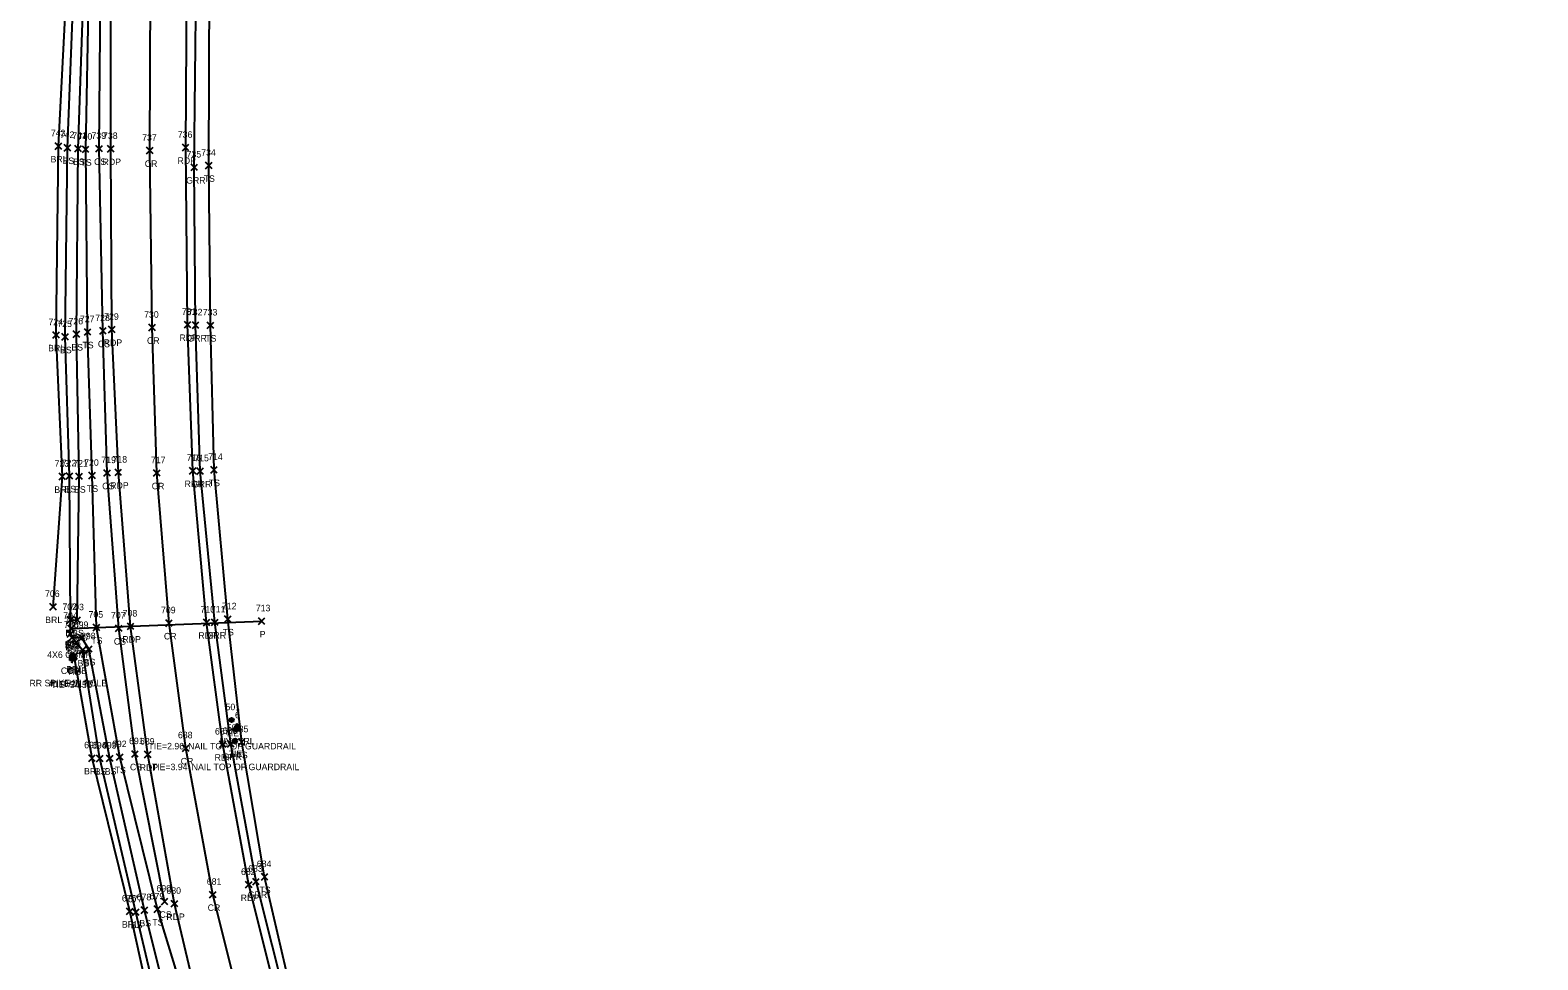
# Model space of a CAD drawing. Extents: x 1879695 to 1880991, y 836466 to 845172.
# Drawn here: x 1879776.2 to 1880237.6, y 844585 to 844869.6 of the extents above; entities that cross this region are included whole.
import ezdxf

# ---------------------------------------------------------------- set-up
doc = ezdxf.new("R2010")
doc.units = 0
for name, color, linetype in [('C_A', 7, 'Continuous'), ('C_C', 7, 'Continuous'), ('C_I', 7, 'Continuous'), ('CBP', 7, 'Continuous'), ('CPBM', 7, 'Continuous'), ('CPSM', 7, 'Continuous'), ('D_A', 7, 'Continuous'), ('D_C', 7, 'Continuous'), ('D_I', 7, 'Continuous'), ('D_TIC', 7, 'Continuous'), ('DCP', 7, 'Continuous'), ('L_A', 7, 'Continuous'), ('L_I', 7, 'Continuous'), ('L_TIC', 7, 'Continuous'), ('LABL', 7, 'Continuous'), ('LELB', 7, 'Continuous'), ('P_A', 7, 'Continuous'), ('P_I', 7, 'Continuous'), ('P_TIC', 7, 'Continuous'), ('PET', 7, 'Continuous'), ('PRC', 7, 'Continuous'), ('R_A', 7, 'Continuous'), ('R_I', 7, 'Continuous'), ('R_TIC', 7, 'Continuous'), ('RGR', 7, 'Continuous'), ('U_A', 7, 'Continuous'), ('U_C', 7, 'Continuous'), ('U_I', 7, 'Continuous'), ('UP', 7, 'Continuous')]:
    doc.layers.add(name, color=color, linetype=linetype)

msp = doc.modelspace()

# ---------------------------------------------------------------- linework, layer by layer
at = {"layer": 'CBP'}
for centre, radius in [((1879789.35, 844677.24), 0.625), ((1879789.35, 844677.24), 0.0833), ((1879837.9, 844658.44), 0.625), ((1879837.9, 844658.44), 0.0833), ((1879838.92, 844652.09), 0.625), ((1879838.92, 844652.09), 0.0833)]:
    msp.add_circle(centre, radius, dxfattribs=at)
at = {"layer": 'CPBM'}
for p, q in [((1879788.92, 844677.25), (1879788.92, 844678.25)), ((1879788.92, 844678.25), (1879789.92, 844678.25)), ((1879789.92, 844677.25), (1879788.92, 844677.25)), ((1879789.42, 844677.75), (1879789.42, 844677.75)), ((1879789.42, 844677.75), (1879789.42, 844677.75)), ((1879789.92, 844678.25), (1879789.92, 844677.25))]:
    msp.add_line(p, q, dxfattribs=at)
at = {"layer": 'CPSM'}
for p, q in [((1879838.29, 844655.25), (1879839.54, 844657.42)), ((1879840.79, 844655.25), (1879839.54, 844657.42)), ((1879839.54, 844655.97), (1879839.54, 844657.42)), ((1879838.29, 844655.25), (1879839.54, 844655.97)), ((1879838.29, 844655.25), (1879840.79, 844655.25)), ((1879839.54, 844655.97), (1879839.54, 844655.97)), ((1879839.54, 844655.97), (1879840.79, 844655.25))]:
    msp.add_line(p, q, dxfattribs=at)
at = {"layer": 'D_TIC'}
for points in [[(1879846.09, 844687.71), (1879848.09, 844689.71)], [(1879848.09, 844687.71), (1879846.09, 844689.71)], [(1879787.78, 844685.43), (1879789.78, 844687.43)], [(1879789.78, 844685.43), (1879787.78, 844687.43)]]:
    msp.add_lwpolyline(points, dxfattribs=at)
at = {"layer": 'DCP'}
msp.add_lwpolyline([(1879788.78, 844686.43), (1879847.09, 844688.71)], dxfattribs=at)
at = {"layer": 'L_TIC'}
for points in [[(1879783.93, 844833.09), (1879785.93, 844835.09)], [(1879785.93, 844833.09), (1879783.93, 844835.09)], [(1879786.69, 844832.58), (1879788.69, 844834.58)], [(1879788.69, 844832.58), (1879786.69, 844834.58)], [(1879789.9, 844832.29), (1879791.9, 844834.29)], [(1879791.9, 844832.29), (1879789.9, 844834.29)], [(1879792.24, 844832.08), (1879794.24, 844834.08)], [(1879794.24, 844832.08), (1879792.24, 844834.08)], [(1879796.37, 844832.31), (1879798.37, 844834.31)], [(1879798.37, 844832.31), (1879796.37, 844834.31)], [(1879829.94, 844827.14), (1879831.94, 844829.14)], [(1879831.94, 844827.14), (1879829.94, 844829.14)], [(1879783.2, 844775.27), (1879785.2, 844777.27)], [(1879785.2, 844775.27), (1879783.2, 844777.27)], [(1879785.93, 844774.7), (1879787.93, 844776.7)], [(1879787.93, 844774.7), (1879785.93, 844776.7)], [(1879789.4, 844775.52), (1879791.4, 844777.52)], [(1879791.4, 844775.52), (1879789.4, 844777.52)], [(1879792.83, 844776.19), (1879794.83, 844778.19)], [(1879794.83, 844776.19), (1879792.83, 844778.19)], [(1879797.52, 844776.54), (1879799.52, 844778.54)], [(1879799.52, 844776.54), (1879797.52, 844778.54)], [(1879830.42, 844778.25), (1879832.42, 844780.25)], [(1879832.42, 844778.25), (1879830.42, 844780.25)], [(1879798.83, 844733.05), (1879800.83, 844735.05)], [(1879800.83, 844733.05), (1879798.83, 844735.05)], [(1879831.5, 844734.02), (1879833.5, 844736.02)], [(1879833.5, 844734.02), (1879831.5, 844736.02)], [(1879785.09, 844731.95), (1879787.09, 844733.95)], [(1879787.09, 844731.95), (1879785.09, 844733.95)], [(1879787.25, 844732.11), (1879789.25, 844734.11)], [(1879789.25, 844732.11), (1879787.25, 844734.11)], [(1879790.23, 844732), (1879792.23, 844734)], [(1879792.23, 844732), (1879790.23, 844734)], [(1879794.21, 844732.25), (1879796.21, 844734.25)], [(1879796.21, 844732.25), (1879794.21, 844734.25)], [(1879782.28, 844692.1), (1879784.28, 844694.1)], [(1879784.28, 844692.1), (1879782.28, 844694.1)], [(1879787.56, 844688.11), (1879789.56, 844690.11)], [(1879789.56, 844688.11), (1879787.56, 844690.11)], [(1879787.56, 844688.11), (1879789.56, 844690.11)], [(1879789.56, 844688.11), (1879787.56, 844690.11)], [(1879789.67, 844688.03), (1879791.67, 844690.03)], [(1879791.67, 844688.03), (1879789.67, 844690.03)], [(1879835.74, 844688.33), (1879837.74, 844690.33)], [(1879837.74, 844688.33), (1879835.74, 844690.33)], [(1879787.58, 844683.77), (1879789.58, 844685.77)], [(1879789.58, 844683.77), (1879787.58, 844685.77)], [(1879788.08, 844682.63), (1879790.08, 844684.63)], [(1879790.08, 844682.63), (1879788.08, 844684.63)], [(1879788.08, 844682.63), (1879790.08, 844684.63)], [(1879790.08, 844682.63), (1879788.08, 844684.63)], [(1879791.03, 844682.6), (1879793.03, 844684.6)], [(1879793.03, 844682.6), (1879791.03, 844684.6)], [(1879795.55, 844685.76), (1879797.55, 844687.76)], [(1879797.55, 844685.76), (1879795.55, 844687.76)], [(1879802.4, 844685.5), (1879804.4, 844687.5)], [(1879804.4, 844685.5), (1879802.4, 844687.5)], [(1879791.29, 844678.84), (1879793.29, 844680.84)], [(1879793.29, 844678.84), (1879791.29, 844680.84)], [(1879793.2, 844679.16), (1879795.2, 844681.16)], [(1879795.2, 844679.16), (1879793.2, 844681.16)], [(1879788.74, 844676.99), (1879790.74, 844678.99)], [(1879790.74, 844676.99), (1879788.74, 844678.99)], [(1879839.98, 844650.69), (1879841.98, 844652.69)], [(1879841.98, 844650.69), (1879839.98, 844652.69)], [(1879794.18, 844645.79), (1879796.18, 844647.79)], [(1879796.18, 844645.79), (1879794.18, 844647.79)], [(1879796.58, 844645.67), (1879798.58, 844647.67)], [(1879798.58, 844645.67), (1879796.58, 844647.67)], [(1879799.64, 844645.71), (1879801.64, 844647.71)], [(1879801.64, 844645.71), (1879799.64, 844647.71)], [(1879802.7, 844646.13), (1879804.7, 844648.13)], [(1879804.7, 844646.13), (1879802.7, 844648.13)], [(1879807.34, 844647.05), (1879809.34, 844649.05)], [(1879809.34, 844647.05), (1879807.34, 844649.05)], [(1879847, 844609.42), (1879849, 844611.42)], [(1879849, 844609.42), (1879847, 844611.42)], [(1879810.24, 844599.26), (1879812.24, 844601.26)], [(1879812.24, 844599.26), (1879810.24, 844601.26)], [(1879814.22, 844599.52), (1879816.22, 844601.52)], [(1879816.22, 844599.52), (1879814.22, 844601.52)], [(1879816.39, 844601.91), (1879818.39, 844603.91)], [(1879818.39, 844601.91), (1879816.39, 844603.91)], [(1879805.77, 844598.89), (1879807.77, 844600.89)], [(1879807.77, 844598.89), (1879805.77, 844600.89)], [(1879807.57, 844598.66), (1879809.57, 844600.66)], [(1879809.57, 844598.66), (1879807.57, 844600.66)]]:
    msp.add_lwpolyline(points, dxfattribs=at)
at = {"layer": 'LABL'}
for points in [[(1879783.28, 844693.1), (1879786.09, 844732.95), (1879784.2, 844776.27), (1879784.93, 844834.09), (1879787.31, 844881.75), (1879789.94, 844927.36), (1879791.41, 844971.14), (1879790.38, 845013.26), (1879792.98, 845052.42), (1879793.87, 845087.6), (1879791.51, 845127.71), (1879794.05, 845166.9)], [(1879838.84, 844478.29), (1879827.4, 844514.75), (1879815.43, 844560.66), (1879806.77, 844599.89), (1879795.18, 844646.79), (1879789.74, 844677.99)]]:
    msp.add_lwpolyline(points, dxfattribs=at)
at = {"layer": 'LELB'}
for points in [[(1879788.56, 844689.11), (1879788.25, 844733.11), (1879786.93, 844775.7), (1879787.69, 844833.58), (1879789.53, 844880.94), (1879792.57, 844929), (1879794.18, 844969.53), (1879792.62, 845014.23), (1879795.86, 845051.75), (1879795.49, 845087.45), (1879795.44, 845126.23), (1879796.98, 845166.46)], [(1879840.74, 844478.66), (1879829.75, 844515.78), (1879817.77, 844560.78), (1879808.57, 844599.66), (1879797.58, 844646.67), (1879792.29, 844679.84), (1879789.08, 844683.63), (1879788.58, 844684.77), (1879788.56, 844689.11), (1879790.67, 844689.03), (1879791.23, 844733), (1879790.4, 844776.52), (1879790.9, 844833.29), (1879792.57, 844880.83), (1879794.66, 844928.51), (1879796.6, 844970.46), (1879795.45, 845013.86), (1879797.69, 845051.68), (1879797.82, 845087.62), (1879798.32, 845126.29), (1879799.71, 845166.01)], [(1879826.86, 844562.48), (1879815.22, 844600.52), (1879803.7, 844647.13), (1879796.55, 844686.76), (1879795.21, 844733.25), (1879793.83, 844777.19), (1879793.24, 844833.08), (1879794.22, 844881.27), (1879796.97, 844928.77), (1879797.73, 844970.48), (1879796.62, 845014.48), (1879799.04, 845050.66), (1879799.3, 845087.57), (1879800.29, 845126.59), (1879801.38, 845165.98)], [(1879892.86, 844475.33), (1879883.81, 844493.88), (1879869.59, 844531.53), (1879857.27, 844570.41), (1879848, 844610.42), (1879840.98, 844651.69), (1879836.74, 844689.33), (1879832.5, 844735.02), (1879831.42, 844779.25), (1879830.94, 844828.14), (1879831.12, 844883.89), (1879831.78, 844926.93), (1879832.17, 844972.31), (1879832.24, 845014.04), (1879832.59, 845051.89), (1879833.37, 845086.82), (1879834.06, 845125.48), (1879835.58, 845163.13)], [(1879817.39, 844602.91), (1879808.34, 844648.05), (1879803.4, 844686.5), (1879799.83, 844734.05), (1879798.52, 844777.54), (1879797.37, 844833.31), (1879797.81, 844880.47), (1879798.76, 844929.8), (1879800.12, 844970.52), (1879800.28, 845015.67), (1879801.11, 845051.3), (1879801.14, 845087.72), (1879800.29, 845126.59)], [(1880237.65, 844030.17), (1880225.55, 844045.25), (1880203.19, 844067.94), (1880175.04, 844095.38), (1880141.55, 844124.24), (1880111.59, 844152.12), (1880079.67, 844179.09), (1880044.89, 844208.16), (1880013.5, 844237.54), (1880003.34, 844247.82), (1879979.16, 844270.62), (1879948.51, 844300.87), (1879928.97, 844335.67), (1879901.59, 844373.87), (1879881.39, 844405.75), (1879863.37, 844445.07), (1879846.41, 844479.41), (1879833.35, 844517.23), (1879821, 844560.9), (1879811.24, 844600.26), (1879800.64, 844646.71), (1879794.2, 844680.16), (1879792.03, 844683.6), (1879789.08, 844683.63)]]:
    msp.add_lwpolyline(points, dxfattribs=at)
at = {"layer": 'P_TIC'}
for points in [[(1879799.91, 844832.26), (1879801.91, 844834.26)], [(1879801.91, 844832.26), (1879799.91, 844834.26)], [(1879811.88, 844831.71), (1879813.88, 844833.71)], [(1879813.88, 844831.71), (1879811.88, 844833.71)], [(1879822.84, 844832.63), (1879824.84, 844834.63)], [(1879824.84, 844832.63), (1879822.84, 844834.63)], [(1879800.26, 844776.93), (1879802.26, 844778.93)], [(1879802.26, 844776.93), (1879800.26, 844778.93)], [(1879812.56, 844777.55), (1879814.56, 844779.55)], [(1879814.56, 844777.55), (1879812.56, 844779.55)], [(1879823.44, 844778.44), (1879825.44, 844780.44)], [(1879825.44, 844778.44), (1879823.44, 844780.44)], [(1879802.24, 844733.23), (1879804.24, 844735.23)], [(1879804.24, 844733.23), (1879802.24, 844735.23)], [(1879814.01, 844733.04), (1879816.01, 844735.04)], [(1879816.01, 844733.04), (1879814.01, 844735.04)], [(1879825.01, 844733.72), (1879827.01, 844735.72)], [(1879827.01, 844733.72), (1879825.01, 844735.72)], [(1879817.74, 844687.1), (1879819.74, 844689.1)], [(1879819.74, 844687.1), (1879817.74, 844689.1)], [(1879829.24, 844687.3), (1879831.24, 844689.3)], [(1879831.24, 844687.3), (1879829.24, 844689.3)], [(1879805.99, 844686.11), (1879807.99, 844688.11)], [(1879807.99, 844686.11), (1879805.99, 844688.11)], [(1879834.2, 844649.98), (1879836.2, 844651.98)], [(1879836.2, 844649.98), (1879834.2, 844651.98)], [(1879811.27, 844646.91), (1879813.27, 844648.91)], [(1879813.27, 844646.91), (1879811.27, 844648.91)], [(1879822.88, 844648.84), (1879824.88, 844650.84)], [(1879824.88, 844648.84), (1879822.88, 844650.84)], [(1879831.13, 844604), (1879833.13, 844606)], [(1879833.13, 844604), (1879831.13, 844606)], [(1879842.17, 844607.03), (1879844.17, 844609.03)], [(1879844.17, 844607.03), (1879842.17, 844609.03)], [(1879819.43, 844601.23), (1879821.43, 844603.23)], [(1879821.43, 844601.23), (1879819.43, 844603.23)]]:
    msp.add_lwpolyline(points, dxfattribs=at)
at = {"layer": 'PET'}
for points in [[(1879829.6, 844563.28), (1879820.43, 844602.23), (1879812.27, 844647.91), (1879806.99, 844687.11), (1879803.24, 844734.23), (1879801.26, 844777.93), (1879800.91, 844833.26), (1879800.95, 844881.46), (1879801.81, 844930.36), (1879801.95, 844971.12), (1879802.52, 845016.02), (1879802.87, 845051.39), (1879803.55, 845087.63), (1879804.52, 845126.21), (1879806.13, 845165.3)], [(1879852.88, 844569.32), (1879843.17, 844608.03), (1879835.2, 844650.98), (1879830.24, 844688.3), (1879826.01, 844734.72), (1879824.44, 844779.44), (1879823.84, 844833.63), (1879824.22, 844883.19), (1879824.83, 844927), (1879825.18, 844971.93), (1879825.59, 845014.41), (1879826.07, 845051.35), (1879826.48, 845086.56), (1879827.38, 845125.9), (1879829.31, 845162.92)]]:
    msp.add_lwpolyline(points, dxfattribs=at)
at = {"layer": 'PRC'}
msp.add_lwpolyline([(1879841.81, 844566.38), (1879832.13, 844605), (1879823.88, 844649.84), (1879818.74, 844688.1), (1879815.01, 844734.04), (1879813.56, 844778.55), (1879812.88, 844832.71), (1879813.07, 844881.95), (1879813.15, 844927.66), (1879813.64, 844971.27), (1879814, 845015.87), (1879814.47, 845051.81), (1879815.09, 845086.96), (1879816.12, 845125.8), (1879818.34, 845164.04)], dxfattribs=at)
at = {"layer": 'R_TIC'}
for points in [[(1879825.48, 844826.6), (1879827.48, 844828.6)], [(1879827.48, 844826.6), (1879825.48, 844828.6)], [(1879825.87, 844778.28), (1879827.87, 844780.28)], [(1879827.87, 844778.28), (1879825.87, 844780.28)], [(1879827.26, 844733.62), (1879829.26, 844735.62)], [(1879829.26, 844733.62), (1879827.26, 844735.62)], [(1879831.76, 844687.35), (1879833.76, 844689.35)], [(1879833.76, 844687.35), (1879831.76, 844689.35)], [(1879836.63, 844650.18), (1879838.63, 844652.18)], [(1879838.63, 844650.18), (1879836.63, 844652.18)], [(1879844.36, 844607.98), (1879846.36, 844609.98)], [(1879846.36, 844607.98), (1879844.36, 844609.98)]]:
    msp.add_lwpolyline(points, dxfattribs=at)
at = {"layer": 'RGR'}
msp.add_lwpolyline([(1879855.21, 844570.01), (1879845.36, 844608.98), (1879837.63, 844651.18), (1879832.76, 844688.35), (1879828.26, 844734.62), (1879826.87, 844779.28), (1879826.48, 844827.6), (1879827.03, 844883.27), (1879827.42, 844927.16), (1879828.14, 844972.18), (1879828.58, 845014.65), (1879828.78, 845051.84), (1879829.43, 845086.81), (1879829.88, 845125.96), (1879831.63, 845162.98)], dxfattribs=at)
at = {"layer": 'UP'}
for p, q in [((1879788.41, 844676.69), (1879788.41, 844678.36)), ((1879788.41, 844678.36), (1879790.08, 844678.36)), ((1879790.08, 844676.69), (1879788.41, 844676.69)), ((1879789, 844675.86), (1879789.25, 844676.69)), ((1879789.5, 844679.19), (1879789.25, 844678.36)), ((1879789.25, 844677.52), (1879789.25, 844677.52)), ((1879790.08, 844678.36), (1879790.08, 844676.69))]:
    msp.add_line(p, q, dxfattribs=at)
msp.add_circle((1879789.25, 844677.52), 0.833, dxfattribs=at)

# ---------------------------------------------------------------- texts
at = {"layer": 'C_A'}
for s, p in [('TIE', (1879787.42, 844672.24)), ('BM', (1879787.73, 844672.75)), ('HVCTRL', (1879834.23, 844650.97)), ('TIE', (1879835.98, 844653.44)), ('TIE', (1879836.99, 844647.09))]:
    msp.add_text(s, height=2, dxfattribs=at).set_placement(p)
at = {"layer": 'C_C'}
for s, p in [('RR SPIKE IN POLE', (1879776.02, 844668.75)), ("TIE=54.51'", (1879782.65, 844668.24)), ("TIE=2.96' NAIL TOP OF GUARDRAIL", (1879812.42, 844649.44)), ("TIE=3.94' NAIL TOP OF GUARDRAIL", (1879813.48, 844643.09))]:
    msp.add_text(s, height=2, dxfattribs=at).set_placement(p)
at = {"layer": 'C_I'}
for s, p in [('502', (1879786.9, 844680.24)), ('826', (1879787, 844680.75)), ('501', (1879836.03, 844661.44)), ('500', (1879836.39, 844655.09)), ('6', (1879838.92, 844658.97))]:
    msp.add_text(s, height=2, dxfattribs=at).set_placement(p)
at = {"layer": 'D_A'}
for p in [(1879846.47, 844683.71), (1879788.16, 844681.43)]:
    msp.add_text('P', height=2, dxfattribs=at).set_placement(p)
at = {"layer": 'D_C'}
msp.add_text('4X6 CGMP', height=2, dxfattribs=at).set_placement((1879781.45, 844677.43))
at = {"layer": 'D_I'}
for s, p in [('713', (1879845.29, 844691.71)), ('704', (1879786.34, 844689.43))]:
    msp.add_text(s, height=2, dxfattribs=at).set_placement(p)
at = {"layer": 'L_A'}
for s, p in [('BRL', (1879782.48, 844829.09)), ('BS', (1879786.13, 844828.58)), ('BS', (1879789.34, 844828.29)), ('TS', (1879791.65, 844828.08)), ('CS', (1879795.81, 844828.31)), ('TS', (1879829.35, 844823.14)), ('BRL', (1879781.74, 844771.27)), ('BS', (1879785.37, 844770.7)), ('BS', (1879788.84, 844771.52)), ('TS', (1879792.24, 844772.19)), ('CS', (1879796.96, 844772.54)), ('TS', (1879829.83, 844774.25)), ('CS', (1879798.27, 844729.05)), ('TS', (1879830.91, 844730.02)), ('BRL', (1879783.63, 844727.95)), ('BS', (1879786.7, 844728.11)), ('BS', (1879789.67, 844728)), ('TS', (1879793.62, 844728.25)), ('BRL', (1879780.83, 844688.1)), ('BS', (1879787, 844684.11)), ('BS', (1879787, 844684.11)), ('BS', (1879789.11, 844684.03)), ('TS', (1879835.15, 844684.33)), ('BS', (1879787.02, 844679.77)), ('BS', (1879787.52, 844678.63)), ('BS', (1879787.52, 844678.63)), ('BS', (1879790.47, 844678.6)), ('TS', (1879794.96, 844681.76)), ('CS', (1879801.84, 844681.5)), ('BS', (1879790.74, 844674.84)), ('BS', (1879792.64, 844675.16)), ('BRL', (1879787.29, 844672.99)), ('TS', (1879839.39, 844646.69)), ('BRL', (1879792.72, 844641.79)), ('BS', (1879796.02, 844641.67)), ('BS', (1879799.08, 844641.71)), ('TS', (1879802.11, 844642.13)), ('CS', (1879806.78, 844643.05)), ('TS', (1879846.41, 844605.42)), ('BRL', (1879804.31, 844594.89)), ('BS', (1879807.01, 844594.66)), ('BS', (1879809.68, 844595.26)), ('TS', (1879813.63, 844595.52)), ('CS', (1879815.83, 844597.91))]:
    msp.add_text(s, height=2, dxfattribs=at).set_placement(p)
at = {"layer": 'L_I'}
for s, p in [('743', (1879782.57, 844837.09)), ('742', (1879785.33, 844836.58)), ('741', (1879789.11, 844836.29)), ('740', (1879790.79, 844836.08)), ('739', (1879795, 844836.31)), ('734', (1879828.58, 844831.14)), ('724', (1879781.84, 844779.27)), ('726', (1879787.98, 844779.52)), ('727', (1879791.47, 844780.19)), ('728', (1879796.15, 844780.54)), ('733', (1879829.06, 844782.25)), ('725', (1879784.56, 844778.7)), ('714', (1879830.7, 844738.02)), ('723', (1879783.73, 844735.95)), ('722', (1879785.89, 844736.11)), ('721', (1879789.43, 844736)), ('720', (1879792.76, 844736.25)), ('719', (1879798.03, 844737.05)), ('706', (1879780.79, 844696.1)), ('702', (1879786.12, 844692.11)), ('702', (1879786.12, 844692.11)), ('703', (1879788.22, 844692.03)), ('712', (1879834.94, 844692.33)), ('701', (1879786.71, 844687.77)), ('705', (1879794.11, 844689.76)), ('707', (1879800.96, 844689.5)), ('700', (1879786.55, 844686.63)), ('700', (1879786.55, 844686.63)), ('699', (1879789.61, 844686.6)), ('697', (1879789.89, 844682.84)), ('698', (1879791.79, 844683.16)), ('696', (1879787.28, 844680.99)), ('685', (1879838.57, 844654.69)), ('692', (1879801.29, 844650.13)), ('691', (1879806.5, 844651.05)), ('695', (1879792.77, 844649.79)), ('694', (1879795.17, 844649.67)), ('693', (1879798.23, 844649.71)), ('684', (1879845.59, 844613.42)), ('690', (1879814.89, 844605.91)), ('676', (1879804.3, 844602.89)), ('677', (1879806.16, 844602.66)), ('678', (1879808.83, 844603.26)), ('679', (1879812.8, 844603.52))]:
    msp.add_text(s, height=2, dxfattribs=at).set_placement(p)
at = {"layer": 'P_A'}
for s, p in [('RDP', (1879798.4, 844828.26)), ('CR', (1879811.31, 844827.71)), ('RDP', (1879821.33, 844828.63)), ('RDP', (1879798.75, 844772.93)), ('CR', (1879811.99, 844773.55)), ('RDP', (1879821.93, 844774.44)), ('RDP', (1879800.73, 844729.23)), ('CR', (1879813.44, 844729.04)), ('RDP', (1879823.5, 844729.72)), ('CR', (1879817.17, 844683.1)), ('RDP', (1879827.73, 844683.3)), ('RDP', (1879804.48, 844682.11)), ('RDP', (1879832.69, 844645.98)), ('RDP', (1879809.76, 844642.91)), ('CR', (1879822.31, 844644.84)), ('CR', (1879830.57, 844600)), ('RDP', (1879840.66, 844603.03)), ('RDP', (1879817.91, 844597.23))]:
    msp.add_text(s, height=2, dxfattribs=at).set_placement(p)
at = {"layer": 'P_I'}
for s, p in [('738', (1879798.55, 844836.26)), ('737', (1879810.51, 844835.71)), ('736', (1879821.42, 844836.63)), ('729', (1879798.89, 844780.93)), ('730', (1879811.11, 844781.55)), ('731', (1879822.65, 844782.44)), ('716', (1879824.16, 844737.72)), ('718', (1879801.44, 844737.23)), ('717', (1879813.21, 844737.04)), ('708', (1879804.55, 844690.11)), ('709', (1879816.29, 844691.1)), ('710', (1879828.36, 844691.3)), ('689', (1879809.86, 844650.91)), ('688', (1879821.47, 844652.84)), ('687', (1879832.79, 844653.98)), ('682', (1879840.76, 844611.03)), ('680', (1879817.93, 844605.23)), ('681', (1879830.29, 844608))]:
    msp.add_text(s, height=2, dxfattribs=at).set_placement(p)
at = {"layer": 'R_A'}
for p in [(1879823.97, 844822.6), (1879824.36, 844774.28), (1879825.75, 844729.62), (1879830.25, 844683.35), (1879835.12, 844646.18), (1879842.85, 844603.98)]:
    msp.add_text('GRR', height=2, dxfattribs=at).set_placement(p)
at = {"layer": 'R_I'}
for s, p in [('735', (1879824.12, 844830.6)), ('732', (1879824.51, 844782.28)), ('715', (1879826.47, 844737.62)), ('711', (1879831.54, 844691.35)), ('686', (1879835.17, 844654.18)), ('683', (1879842.95, 844611.98))]:
    msp.add_text(s, height=2, dxfattribs=at).set_placement(p)
at = {"layer": 'U_A'}
msp.add_text('COMB', height=2, dxfattribs=at).set_placement((1879785.63, 844672.52))
at = {"layer": 'U_C'}
msp.add_text('#110/2/170', height=2, dxfattribs=at).set_placement((1879781.98, 844668.52))
at = {"layer": 'U_I'}
msp.add_text('503', height=2, dxfattribs=at).set_placement((1879786.81, 844680.52))

doc.saveas('drawing.dxf')
